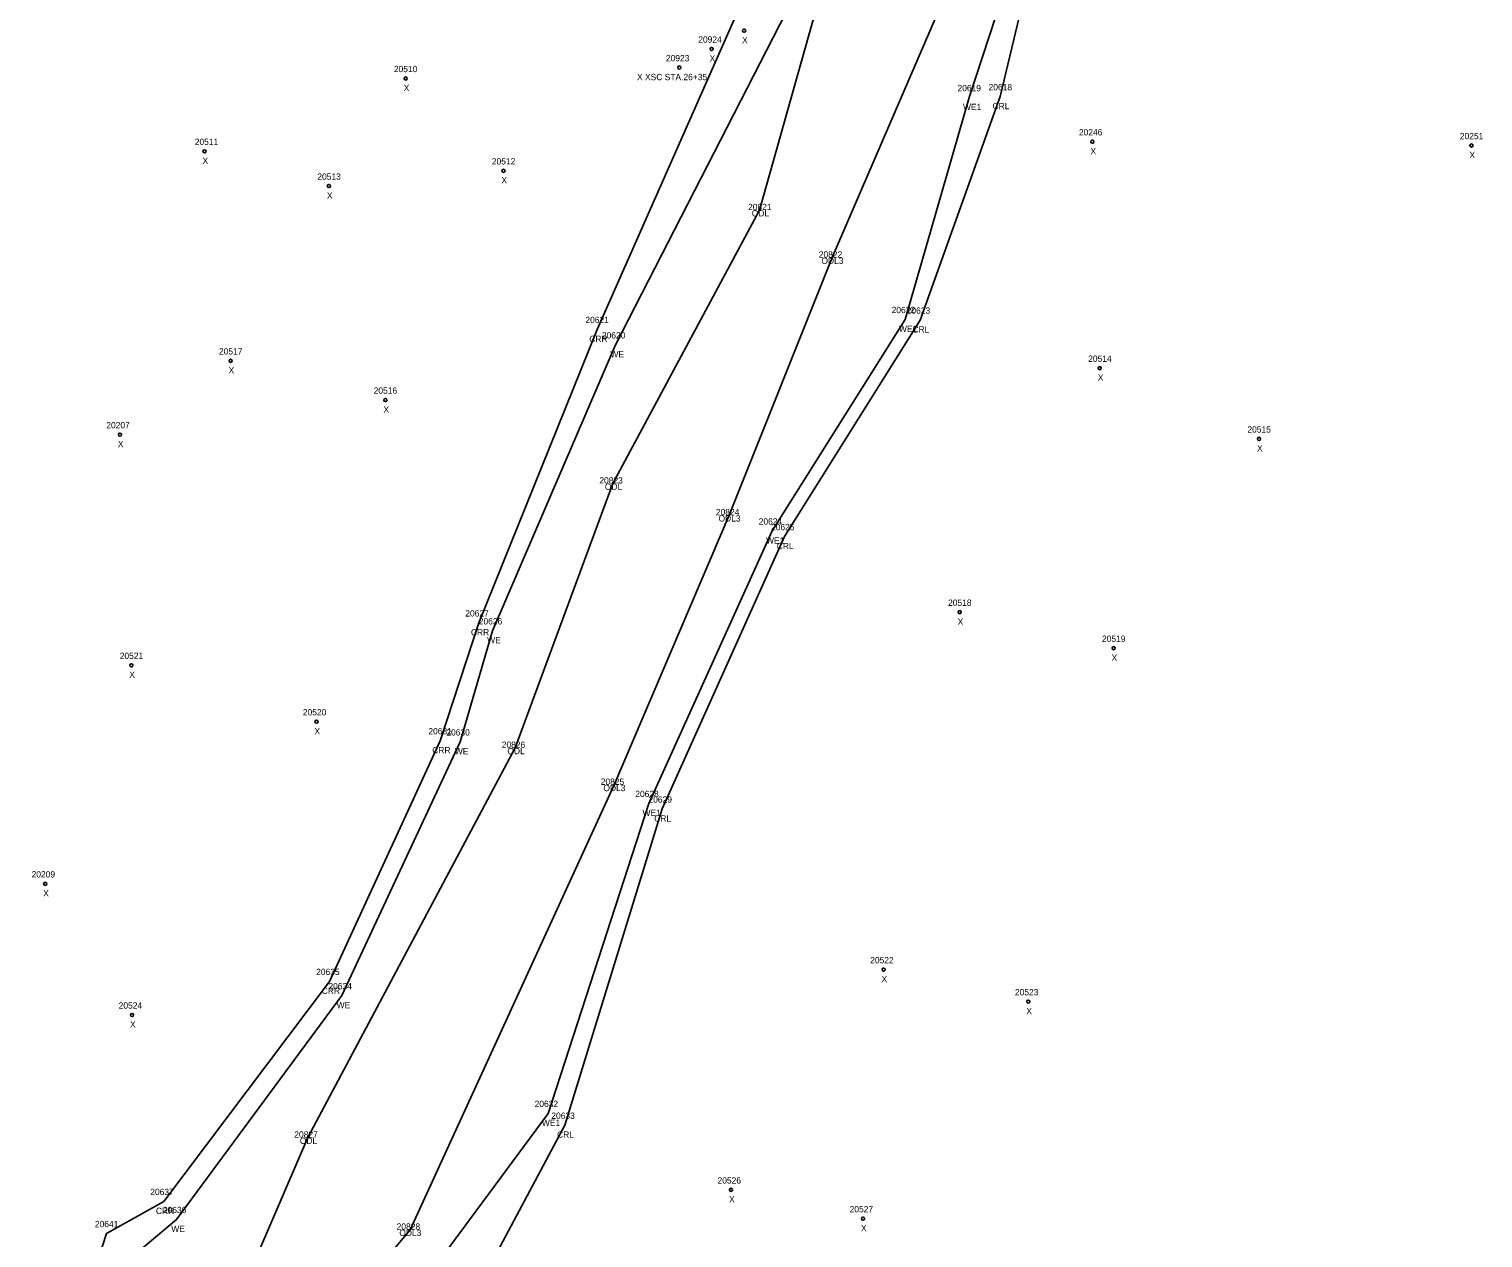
# Model space of a CAD drawing. Extents: x 1966740 to 1969291, y 1117378 to 1118461.
# Drawn here: x 1967715 to 1967945.5, y 1117610.5 to 1117802.2 of the extents above; entities that cross this region are included whole.
import ezdxf

# ---------------------------------------------------------------- set-up
doc = ezdxf.new("R2010")
doc.units = 0
for name, color, linetype in [('RD_EX_H2O', 7, 'Continuous'), ('RD_EX_H2O_txCode', 7, 'Continuous'), ('RD_SMD_Locator', 7, 'Continuous'), ('RD_SMD_Misc', 7, 'Continuous')]:
    doc.layers.add(name, color=color, linetype=linetype)

msp = doc.modelspace()

# ---------------------------------------------------------------- linework, layer by layer
at = {"layer": 'RD_EX_H2O'}
for points in [[(1967837.87, 1118086.59), (1967816.35, 1118042.52), (1967807.65, 1118000.54), (1967802.25, 1117964.95), (1967802.7, 1117929.05), (1967808.24, 1117891.66), (1967818.1, 1117847.27), (1967841.92, 1117812.91), (1967830.83, 1117773.47), (1967807.55, 1117730.13), (1967792.1, 1117688.21), (1967759.2, 1117626.42), (1967746.8, 1117597.58), (1967728.31, 1117575.82), (1967748.97, 1117519.79), (1967787.59, 1117491.86), (1967802.7, 1117484.72), (1967813.63, 1117479.24)], [(1967846.86, 1118079.71), (1967831.29, 1118034.88), (1967818.84, 1117997.76), (1967815.72, 1117964.67), (1967820.18, 1117928.06), (1967829.19, 1117896.79), (1967834.11, 1117854.1), (1967863.47, 1117815.02), (1967842.32, 1117765.95), (1967826.02, 1117725.1), (1967807.77, 1117682.35), (1967775.42, 1117611.81), (1967754.74, 1117587.12), (1967745.94, 1117565.65), (1967761.23, 1117525.28), (1967787.1, 1117502.15), (1967805.18, 1117494.11), (1967821.41, 1117490.36)], [(1967794.3, 1117875.45), (1967796.63, 1117853.43), (1967809.67, 1117835.4), (1967828.83, 1117808.28), (1967805.08, 1117754.56), (1967786.33, 1117708.04), (1967780.19, 1117689.35), (1967762.68, 1117651.19), (1967736.39, 1117616.3), (1967727.33, 1117611.21), (1967715.04, 1117573.35), (1967731.01, 1117514.73), (1967775.86, 1117468.11), (1967793.29, 1117458.88), (1967816.39, 1117454.18)], [(1967873.55, 1117813.3), (1967873.54, 1117810.73), (1967868.98, 1117791.48), (1967856.29, 1117756.05), (1967834.78, 1117721.72), (1967815.36, 1117678.52), (1967799.96, 1117628.39), (1967778.25, 1117587.63), (1967771.33, 1117582.11), (1967756.46, 1117564.6), (1967764.36, 1117543.85), (1967795.97, 1117517.33), (1967805.92, 1117513.21), (1967828.95, 1117503.56)], [(1967837.15, 1117809.04), (1967808.01, 1117752.12), (1967788.48, 1117706.78), (1967783.36, 1117689.17), (1967764.63, 1117648.93), (1967738.42, 1117613.44), (1967731.11, 1117607.31), (1967718.77, 1117573.47), (1967736.01, 1117517.29), (1967781.71, 1117484.69), (1967799.34, 1117478.73), (1967814.43, 1117469.18)], [(1967870.38, 1117810.73), (1967864.06, 1117791.33), (1967853.89, 1117756.14), (1967832.83, 1117722.61), (1967813.26, 1117679.41), (1967797.31, 1117630.26), (1967771.82, 1117595.7), (1967769.03, 1117583.97), (1967753.91, 1117565.22), (1967760.74, 1117542.39), (1967793.79, 1117511.28), (1967804.07, 1117502.92), (1967828.12, 1117499.18)]]:
    msp.add_lwpolyline(points, dxfattribs=at)
at = {"layer": 'RD_SMD_Locator'}
for centre, radius in [((1967828.37, 1117801.92), 0.25), ((1967823.23, 1117799.03), 0.25), ((1967818.1, 1117796.08), 0.25), ((1967774.73, 1117794.35), 0.25), ((1967864.06, 1117791.33), 0.001), ((1967868.98, 1117791.48), 0.001), ((1967883.58, 1117784.32), 0.25), ((1967943.66, 1117783.72), 0.25), ((1967742.85, 1117782.8), 0.25), ((1967790.23, 1117779.71), 0.25), ((1967762.56, 1117777.29), 0.25), ((1967830.83, 1117773.47), 0.001), ((1967842.32, 1117765.95), 0.001), ((1967853.89, 1117756.14), 0.001), ((1967856.29, 1117756.05), 0.001), ((1967805.08, 1117754.56), 0.001), ((1967808.01, 1117752.12), 0.001), ((1967746.98, 1117749.58), 0.25), ((1967884.74, 1117748.42), 0.25), ((1967771.52, 1117743.36), 0.25), ((1967729.44, 1117737.88), 0.25), ((1967909.99, 1117737.2), 0.25), ((1967807.55, 1117730.13), 0.001), ((1967826.02, 1117725.1), 0.001), ((1967832.83, 1117722.61), 0.001), ((1967834.78, 1117721.72), 0.001), ((1967862.54, 1117709.73), 0.25), ((1967786.33, 1117708.04), 0.001), ((1967788.48, 1117706.78), 0.001), ((1967886.94, 1117704.02), 0.25), ((1967731.25, 1117701.31), 0.25), ((1967760.59, 1117692.36), 0.25), ((1967780.19, 1117689.35), 0.001), ((1967783.36, 1117689.17), 0.001), ((1967792.1, 1117688.21), 0.001), ((1967807.77, 1117682.35), 0.001), ((1967813.26, 1117679.41), 0.001), ((1967815.36, 1117678.52), 0.001), ((1967717.6, 1117666.66), 0.25), ((1967850.48, 1117653.05), 0.25), ((1967762.68, 1117651.19), 0.001), ((1967764.63, 1117648.93), 0.001), ((1967873.42, 1117647.98), 0.25), ((1967731.36, 1117645.86), 0.25), ((1967797.31, 1117630.26), 0.001), ((1967799.96, 1117628.39), 0.001), ((1967759.2, 1117626.42), 0.001), ((1967826.3, 1117618.13), 0.25), ((1967736.39, 1117616.3), 0.001), ((1967738.42, 1117613.44), 0.001), ((1967847.21, 1117613.56), 0.25), ((1967727.33, 1117611.21), 0.001), ((1967775.42, 1117611.81), 0.001)]:
    msp.add_circle(centre, radius, dxfattribs=at)

# ---------------------------------------------------------------- texts
at = {"layer": 'RD_EX_H2O_txCode'}
for s, p in [('20619', (1967862.2, 1117792.33)), ('20618', (1967867.12, 1117792.48)), ('CRL', (1967867.75, 1117789.48)), ('WE1', (1967863.07, 1117789.33)), ('20821', (1967829, 1117773.47)), ('ODL', (1967829.59, 1117772.47)), ('20822', (1967840.21, 1117765.95)), ('ODL3', (1967840.63, 1117764.95)), ('20622', (1967851.75, 1117757.14)), ('20621', (1967803.22, 1117755.56)), ('20623', (1967854.15, 1117757.05)), ('CRR', (1967803.83, 1117752.56)), ('20620', (1967805.83, 1117753.12)), ('WE1', (1967852.91, 1117754.14)), ('CRL', (1967855.06, 1117754.05)), ('WE', (1967807.18, 1117750.12)), ('20823', (1967805.43, 1117730.13)), ('ODL', (1967806.3, 1117729.13)), ('20824', (1967823.9, 1117725.1)), ('ODL3', (1967824.32, 1117724.1)), ('20624', (1967830.69, 1117723.61)), ('20625', (1967832.64, 1117722.72)), ('WE1', (1967831.85, 1117720.61)), ('CRL', (1967833.55, 1117719.72)), ('20627', (1967784.18, 1117709.04)), ('20626', (1967786.32, 1117707.78)), ('CRR', (1967785.07, 1117706.04)), ('WE', (1967787.65, 1117704.78)), ('20631', (1967778.33, 1117690.35)), ('20630', (1967781.18, 1117690.17)), ('20826', (1967789.96, 1117688.21)), ('CRR', (1967778.94, 1117687.35)), ('WE', (1967782.52, 1117687.17)), ('ODL', (1967790.85, 1117687.21)), ('20825', (1967805.65, 1117682.35)), ('ODL3', (1967806.07, 1117681.35)), ('20628', (1967811.12, 1117680.41)), ('20629', (1967813.22, 1117679.52)), ('WE1', (1967812.27, 1117677.41)), ('CRL', (1967814.13, 1117676.52)), ('20635', (1967760.54, 1117652.19)), ('CRR', (1967761.43, 1117649.19)), ('20634', (1967762.49, 1117649.93)), ('WE', (1967763.79, 1117646.93)), ('20632', (1967795.17, 1117631.26)), ('WE1', (1967796.32, 1117628.26)), ('20633', (1967797.82, 1117629.39)), ('20827', (1967757.08, 1117626.42)), ('CRL', (1967798.73, 1117626.39)), ('ODL', (1967757.95, 1117625.42)), ('20637', (1967734.25, 1117617.3)), ('CRR', (1967735.14, 1117614.3)), ('20636', (1967736.25, 1117614.44)), ('20641', (1967725.47, 1117612.21)), ('WE', (1967737.58, 1117611.44)), ('20828', (1967773.3, 1117611.81)), ('ODL3', (1967773.72, 1117610.81))]:
    msp.add_text(s, height=1, dxfattribs=at).set_placement(p)
at = {"layer": 'RD_SMD_Misc'}
for s, p in [('20924', (1967821.11, 1117800.03)), ('X', (1967828.05, 1117799.92)), ('20923', (1967815.98, 1117797.08)), ('X', (1967822.91, 1117797.03)), ('20510', (1967772.86, 1117795.35)), ('X XSC STA.26+35', (1967811.4, 1117794.08)), ('X', (1967774.42, 1117792.35)), ('20246', (1967881.44, 1117785.32)), ('20511', (1967741.3, 1117783.8)), ('20251', (1967941.82, 1117784.72)), ('X', (1967742.53, 1117780.8)), ('20512', (1967788.39, 1117780.71)), ('X', (1967883.27, 1117782.32)), ('X', (1967943.34, 1117781.72)), ('20513', (1967760.73, 1117778.29)), ('X', (1967789.91, 1117777.71)), ('X', (1967762.25, 1117775.29)), ('20517', (1967745.14, 1117750.58)), ('20514', (1967882.91, 1117749.42)), ('X', (1967746.66, 1117747.58)), ('X', (1967884.43, 1117746.42)), ('20516', (1967769.66, 1117744.36)), ('X', (1967771.21, 1117741.36)), ('20207', (1967727.28, 1117738.88)), ('20515', (1967908.15, 1117738.2)), ('X', (1967729.12, 1117735.88)), ('X', (1967909.67, 1117735.2)), ('20518', (1967860.7, 1117710.73)), ('X', (1967862.22, 1117707.73)), ('20519', (1967885.1, 1117705.02)), ('20521', (1967729.41, 1117702.31)), ('X', (1967886.62, 1117702.02)), ('X', (1967730.93, 1117699.31)), ('20520', (1967758.43, 1117693.36)), ('X', (1967760.27, 1117690.36)), ('20209', (1967715.44, 1117667.66)), ('X', (1967717.28, 1117664.66)), ('20522', (1967848.36, 1117654.05)), ('X', (1967850.16, 1117651.05)), ('20523', (1967871.3, 1117648.98)), ('20524', (1967729.24, 1117646.86)), ('X', (1967873.11, 1117645.98)), ('X', (1967731.04, 1117643.86)), ('20526', (1967824.16, 1117619.13)), ('X', (1967825.99, 1117616.13)), ('20527', (1967845.1, 1117614.56)), ('X', (1967846.9, 1117611.56))]:
    msp.add_text(s, height=1, dxfattribs=at).set_placement(p)

doc.saveas('drawing.dxf')
